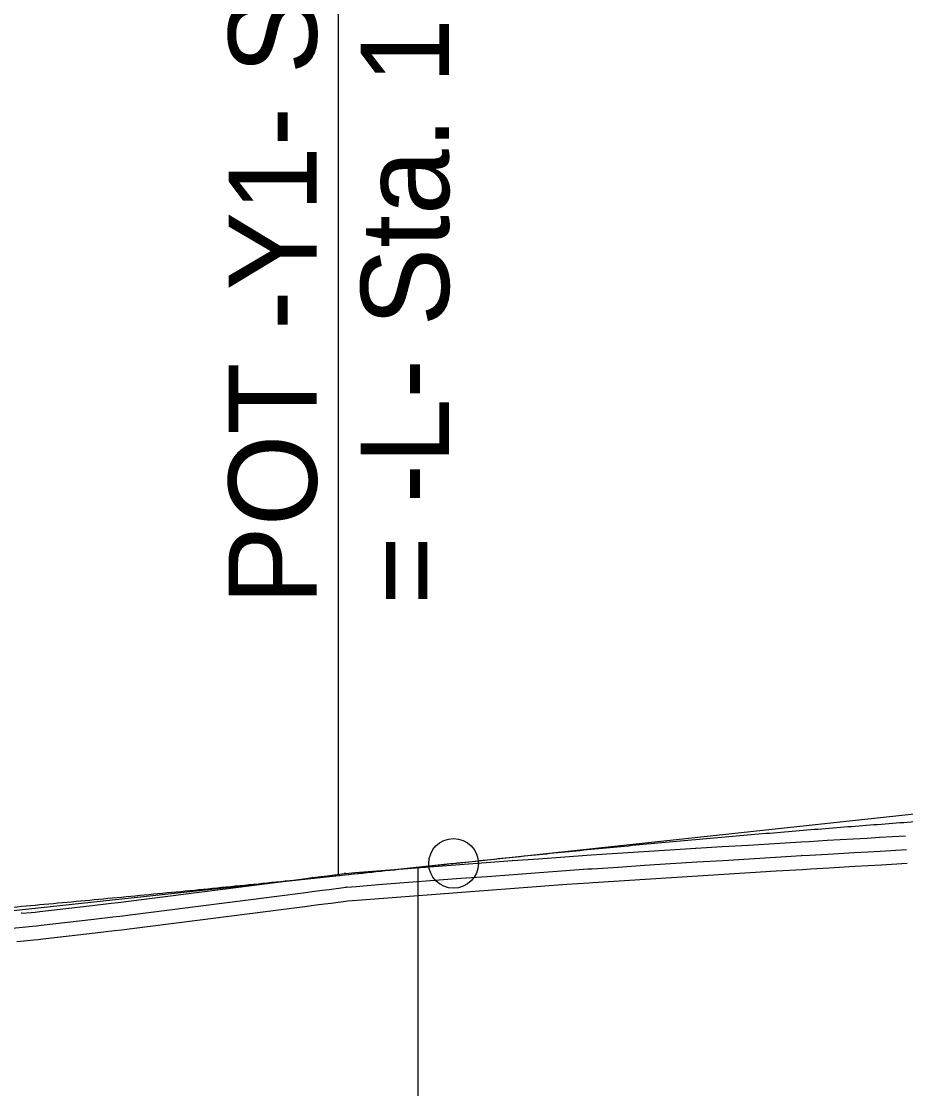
# Model space of a CAD drawing. Extents: x 1625686 to 1640492, y 1161393 to 1175642.
# Drawn here: x 1631055.1 to 1631135.3, y 1175003.6 to 1175100.4 of the extents above; entities that cross this region are included whole.
import ezdxf

# ---------------------------------------------------------------- set-up
doc = ezdxf.new("R2010")
doc.units = 0
for name, color, linetype in [('Exist Vertical Profile Ground Line', 7, 'Continuous'), ('Prop PFL Text', 7, 'Continuous'), ('Prop Vertical Profile Curve Label', 7, 'Continuous'), ('Prop Vertical Profile Grade', 7, 'Continuous'), ('Prop VPI Label', 7, 'Continuous'), ('Scratch_Level_1', 7, 'Continuous'), ('Scratch_Level_5', 7, 'Continuous')]:
    doc.layers.add(name, color=color, linetype=linetype)

msp = doc.modelspace()

# ---------------------------------------------------------------- linework, layer by layer
at = {"layer": 'Exist Vertical Profile Ground Line'}
msp.add_lwpolyline([(1631054.685, 1175016.921), (1631055.335, 1175016.981), (1631056.227, 1175017.063), (1631056.621, 1175017.098), (1631057.061, 1175017.149), (1631059.438, 1175017.425), (1631061.814, 1175017.702), (1631063.548, 1175017.904), (1631064.19, 1175017.985), (1631066.566, 1175018.285), (1631068.942, 1175018.585), (1631071.318, 1175018.887), (1631073.695, 1175019.189), (1631076.071, 1175019.492), (1631078.447, 1175019.797), (1631080.823, 1175020.102), (1631081.849, 1175020.234), (1631082.595, 1175020.325), (1631083.199, 1175020.405), (1631084.72, 1175020.605), (1631085.575, 1175020.672), (1631087.952, 1175020.857), (1631090.328, 1175021.04), (1631092.704, 1175021.222), (1631095.08, 1175021.401), (1631097.456, 1175021.579), (1631099.832, 1175021.755), (1631102.209, 1175021.93), (1631104.585, 1175022.102), (1631106.586, 1175022.246), (1631106.961, 1175022.271), (1631109.337, 1175022.426), (1631111.713, 1175022.579), (1631114.09, 1175022.73), (1631116.466, 1175022.88), (1631118.842, 1175023.028), (1631121.218, 1175023.174), (1631123.594, 1175023.318), (1631125.97, 1175023.46), (1631126.713, 1175023.504), (1631128.347, 1175023.6), (1631130.723, 1175023.736), (1631131.968, 1175023.807), (1631133.099, 1175023.874), (1631135.475, 1175024.013)], dxfattribs=at)
at = {"layer": 'Prop PFL Text'}
for p, q in [((1631083.884, 1175022.983), (1631083.884, 1175169.212)), ((1631091.115, 1174877.433), (1631091.115, 1175023.662))]:
    msp.add_line(p, q, dxfattribs=at)
at = {"layer": 'Prop Vertical Profile Curve Label'}
msp.add_circle((1631094.314, 1175024.002), 2.25, dxfattribs=at)
msp.add_circle((1631094.314, 1175024.002), 2.25, dxfattribs=at)
at = {"layer": 'Prop Vertical Profile Grade'}
for points in [[(1631094.314, 1175024.002), (1631099.714, 1175024.571), (1631105.114, 1175025.117), (1631110.514, 1175025.639), (1631115.914, 1175026.138), (1631121.314, 1175026.613), (1631126.714, 1175027.064), (1631132.114, 1175027.492), (1631137.514, 1175027.896), (1631142.914, 1175028.276), (1631148.314, 1175028.633), (1631153.714, 1175028.966), (1631159.114, 1175029.275), (1631164.514, 1175029.56), (1631169.914, 1175029.822), (1631175.314, 1175030.061), (1631180.714, 1175030.275), (1631186.114, 1175030.466), (1631191.514, 1175030.634), (1631196.914, 1175030.777), (1631202.314, 1175030.898), (1631207.714, 1175030.994), (1631213.114, 1175031.067), (1631218.514, 1175031.116), (1631223.914, 1175031.141), (1631229.314, 1175031.143), (1631234.714, 1175031.121), (1631240.114, 1175031.075), (1631245.514, 1175031.006), (1631250.914, 1175030.913), (1631256.314, 1175030.796), (1631261.714, 1175030.656), (1631267.114, 1175030.492), (1631272.514, 1175030.305), (1631277.914, 1175030.093), (1631283.314, 1175029.859), (1631288.714, 1175029.6), (1631294.114, 1175029.318), (1631299.514, 1175029.012), (1631304.914, 1175028.682), (1631310.314, 1175028.329), (1631315.714, 1175027.952), (1631321.114, 1175027.552), (1631326.514, 1175027.128), (1631331.914, 1175026.68), (1631337.314, 1175026.208), (1631342.714, 1175025.713), (1631348.114, 1175025.194), (1631353.514, 1175024.652), (1631358.914, 1175024.086), (1631364.314, 1175023.496)], [(1630764.314, 1175011.328), (1630770.914, 1175011.134), (1630777.514, 1175010.958), (1630784.114, 1175010.8), (1630790.714, 1175010.66), (1630797.314, 1175010.539), (1630803.914, 1175010.435), (1630810.514, 1175010.351), (1630817.114, 1175010.284), (1630823.714, 1175010.236), (1630830.314, 1175010.206), (1630836.914, 1175010.194), (1630843.514, 1175010.201), (1630850.114, 1175010.226), (1630856.714, 1175010.269), (1630863.314, 1175010.33), (1630869.914, 1175010.41), (1630876.514, 1175010.508), (1630883.114, 1175010.625), (1630889.714, 1175010.759), (1630896.314, 1175010.912), (1630902.914, 1175011.083), (1630909.514, 1175011.273), (1630916.114, 1175011.48), (1630922.714, 1175011.706), (1630929.314, 1175011.951), (1630935.914, 1175012.213), (1630942.514, 1175012.494), (1630949.114, 1175012.793), (1630955.714, 1175013.111), (1630962.314, 1175013.447), (1630968.914, 1175013.801), (1630975.514, 1175014.173), (1630982.114, 1175014.564), (1630988.714, 1175014.973), (1630995.314, 1175015.4), (1631001.914, 1175015.845), (1631008.514, 1175016.309), (1631015.114, 1175016.791), (1631021.714, 1175017.291), (1631028.314, 1175017.81), (1631034.914, 1175018.347), (1631041.514, 1175018.902), (1631048.114, 1175019.475), (1631054.714, 1175020.067), (1631061.314, 1175020.677), (1631067.914, 1175021.305), (1631074.514, 1175021.952), (1631081.114, 1175022.617), (1631087.714, 1175023.3), (1631094.314, 1175024.002)]]:
    msp.add_spline(points, degree=3, dxfattribs=at)
at = {"layer": 'Prop VPI Label'}
for q in [(1631226.58, 1175038.242), (1630932.048, 1175006.531)]:
    msp.add_line((1631094.314, 1175024.002), q, dxfattribs=at)
at = {"layer": 'Scratch_Level_1'}
for p, q in [((1631118.689, 1175025.523), (1631121.065, 1175025.669)), ((1631121.067, 1175025.669), (1631123.443, 1175025.813)), ((1631123.445, 1175025.814), (1631125.821, 1175025.956)), ((1631125.823, 1175025.956), (1631126.565, 1175026)), ((1631126.567, 1175026), (1631128.201, 1175026.095)), ((1631128.203, 1175026.095), (1631130.579, 1175026.232)), ((1631132.953, 1175026.37), (1631135.329, 1175026.508)), ((1631102.028, 1175024.423), (1631104.404, 1175024.596)), ((1631104.406, 1175024.596), (1631106.407, 1175024.739)), ((1631106.421, 1175024.74), (1631106.796, 1175024.765)), ((1631106.798, 1175024.765), (1631109.175, 1175024.92)), ((1631109.176, 1175024.92), (1631111.553, 1175025.074)), ((1631111.554, 1175025.074), (1631113.931, 1175025.225)), ((1631113.932, 1175025.225), (1631116.309, 1175025.375)), ((1631116.31, 1175025.375), (1631118.687, 1175025.523)), ((1631123.519, 1175024.566), (1631125.896, 1175024.708)), ((1631125.897, 1175024.708), (1631126.639, 1175024.752)), ((1631126.64, 1175024.752), (1631128.274, 1175024.847)), ((1631128.275, 1175024.848), (1631130.651, 1175024.984)), ((1631133.026, 1175025.122), (1631135.402, 1175025.261)), ((1631090.137, 1175023.533), (1631092.514, 1175023.715)), ((1631092.515, 1175023.715), (1631094.892, 1175023.894)), ((1631094.894, 1175023.894), (1631097.27, 1175024.072)), ((1631097.272, 1175024.072), (1631099.648, 1175024.249)), ((1631099.65, 1175024.249), (1631102.026, 1175024.423)), ((1631106.88, 1175023.518), (1631109.256, 1175023.673)), ((1631109.257, 1175023.673), (1631111.633, 1175023.826)), ((1631111.634, 1175023.826), (1631114.01, 1175023.978)), ((1631114.011, 1175023.978), (1631116.387, 1175024.127)), ((1631116.388, 1175024.127), (1631118.764, 1175024.275)), ((1631118.765, 1175024.275), (1631121.141, 1175024.421)), ((1631121.142, 1175024.421), (1631123.519, 1175024.566)), ((1631084.525, 1175023.097), (1631085.38, 1175023.165)), ((1631085.381, 1175023.165), (1631087.758, 1175023.35)), ((1631087.759, 1175023.35), (1631090.136, 1175023.533)), ((1631092.61, 1175022.468), (1631094.986, 1175022.648)), ((1631094.987, 1175022.648), (1631097.363, 1175022.826)), ((1631097.364, 1175022.826), (1631099.74, 1175023.002)), ((1631099.741, 1175023.002), (1631102.117, 1175023.176)), ((1631102.118, 1175023.176), (1631104.494, 1175023.349)), ((1631104.495, 1175023.349), (1631106.496, 1175023.493)), ((1631106.504, 1175023.493), (1631106.879, 1175023.518)), ((1631084.622, 1175021.851), (1631085.478, 1175021.918)), ((1631085.478, 1175021.918), (1631087.855, 1175022.103)), ((1631087.856, 1175022.103), (1631090.232, 1175022.287)), ((1631090.233, 1175022.287), (1631092.609, 1175022.468)), ((1631055.107, 1175019.471), (1631055.999, 1175019.552)), ((1631055.221, 1175018.226), (1631056.113, 1175018.307))]:
    msp.add_line(p, q, dxfattribs=at)
for points in [[(1631130.581, 1175026.232), (1631131.823, 1175026.303), (1631132.951, 1175026.369)], [(1631130.652, 1175024.984), (1631131.896, 1175025.055), (1631133.025, 1175025.122)], [(1631056.001, 1175019.552), (1631056.364, 1175019.585), (1631056.774, 1175019.633), (1631059.149, 1175019.908), (1631061.524, 1175020.185), (1631063.247, 1175020.386), (1631063.878, 1175020.465), (1631066.253, 1175020.765), (1631068.628, 1175021.065), (1631071.003, 1175021.367), (1631073.378, 1175021.669), (1631075.754, 1175021.972), (1631078.129, 1175022.276), (1631080.504, 1175022.582), (1631081.529, 1175022.714)], [(1631081.546, 1175022.716), (1631082.281, 1175022.805), (1631082.873, 1175022.883), (1631084.394, 1175023.084)], [(1631081.698, 1175021.475), (1631082.438, 1175021.565), (1631083.036, 1175021.644), (1631084.557, 1175021.844)], [(1631056.114, 1175018.307), (1631056.492, 1175018.342), (1631056.917, 1175018.391), (1631059.293, 1175018.667), (1631061.669, 1175018.943), (1631063.397, 1175019.145), (1631064.034, 1175019.225), (1631066.409, 1175019.525), (1631068.785, 1175019.825), (1631071.161, 1175020.127), (1631073.536, 1175020.429), (1631075.912, 1175020.732), (1631078.288, 1175021.037), (1631080.664, 1175021.342), (1631081.689, 1175021.474)], [(1631030.172, 1175015.955), (1631030.813, 1175016.011), (1631033.189, 1175016.222), (1631035.564, 1175016.434), (1631037.94, 1175016.647), (1631040.316, 1175016.861), (1631042.854, 1175017.09), (1631045.067, 1175017.292), (1631047.443, 1175017.509), (1631049.818, 1175017.727), (1631052.194, 1175017.946), (1631054.57, 1175018.165), (1631055.22, 1175018.226)]]:
    msp.add_lwpolyline(points, dxfattribs=at)
for centre, radius, start, end in [((1631121.218, 1175023.174), 2.5, 93.4746, 93.51747), ((1631123.594, 1175023.318), 2.5, 93.43169, 93.4746), ((1631125.97, 1175023.46), 2.5, 93.38873, 93.43169), ((1631126.713, 1175023.504), 2.5, 93.33274, 93.38873), ((1631128.347, 1175023.6), 2.5, 93.29095, 93.33274), ((1631130.723, 1175023.736), 2.5, 93.24912, 93.29095), ((1631133.099, 1175023.874), 2.5, 93.34509, 93.38704), ((1631104.585, 1175022.102), 2.5, 94.10418, 94.15337), ((1631106.586, 1175022.246), 2.5, 93.77378, 94.10418), ((1631106.961, 1175022.271), 2.5, 93.73117, 93.77378), ((1631109.337, 1175022.426), 2.5, 93.68852, 93.73117), ((1631111.713, 1175022.579), 2.5, 93.64582, 93.68852), ((1631114.09, 1175022.73), 2.5, 93.60308, 93.64582), ((1631116.466, 1175022.88), 2.5, 93.5603, 93.60308), ((1631118.842, 1175023.028), 2.5, 93.51747, 93.5603), ((1631125.97, 1175023.46), 1.25, 93.38873, 93.43169), ((1631126.713, 1175023.504), 1.25, 93.33274, 93.38873), ((1631128.347, 1175023.6), 1.25, 93.29095, 93.33274), ((1631130.723, 1175023.736), 1.25, 93.24912, 93.29095), ((1631133.099, 1175023.874), 1.25, 93.34509, 93.38704), ((1631092.704, 1175021.222), 2.5, 94.32362, 94.36605), ((1631095.08, 1175021.401), 2.5, 94.28113, 94.32362), ((1631097.456, 1175021.579), 2.5, 94.2386, 94.28113), ((1631099.832, 1175021.755), 2.5, 94.19601, 94.2386), ((1631102.209, 1175021.93), 2.5, 94.15337, 94.19601), ((1631109.337, 1175022.426), 1.25, 93.68852, 93.73117), ((1631111.713, 1175022.579), 1.25, 93.64582, 93.68852), ((1631114.09, 1175022.73), 1.25, 93.60308, 93.64582), ((1631116.466, 1175022.88), 1.25, 93.5603, 93.60308), ((1631118.842, 1175023.028), 1.25, 93.51747, 93.5603), ((1631121.218, 1175023.174), 1.25, 93.4746, 93.51747), ((1631123.594, 1175023.318), 1.25, 93.43169, 93.4746), ((1631081.849, 1175020.234), 2.5, 96.95013, 97.34369), ((1631084.72, 1175020.605), 2.5, 94.49303, 97.50913), ((1631085.575, 1175020.672), 2.5, 94.45076, 94.49303), ((1631087.952, 1175020.857), 2.5, 94.40843, 94.45076), ((1631090.328, 1175021.04), 2.5, 94.36605, 94.40843), ((1631095.08, 1175021.401), 1.25, 94.28113, 94.32362), ((1631097.456, 1175021.579), 1.25, 94.2386, 94.28113), ((1631099.832, 1175021.755), 1.25, 94.19601, 94.2386), ((1631102.209, 1175021.93), 1.25, 94.15337, 94.19601), ((1631104.585, 1175022.102), 1.25, 94.10418, 94.15337), ((1631106.586, 1175022.246), 1.25, 93.77378, 94.10418), ((1631106.961, 1175022.271), 1.25, 93.73117, 93.77378), ((1631084.72, 1175020.605), 1.25, 94.49303, 97.50913), ((1631085.575, 1175020.672), 1.25, 94.45076, 94.49303), ((1631087.952, 1175020.857), 1.25, 94.40843, 94.45076), ((1631090.328, 1175021.04), 1.25, 94.36605, 94.40843), ((1631092.704, 1175021.222), 1.25, 94.32362, 94.36605), ((1631081.849, 1175020.234), 1.25, 96.95013, 97.34369), ((1631055.335, 1175016.981), 2.5, 95.23039, 95.3055), ((1631056.227, 1175017.063), 2.5, 95.19818, 95.23039), ((1631055.335, 1175016.981), 1.25, 95.23039, 95.3055), ((1631056.227, 1175017.063), 1.25, 95.19818, 95.23039)]:
    msp.add_arc(centre, radius, start, end, dxfattribs=at)
at = {"layer": 'Scratch_Level_5'}
msp.add_lwpolyline([(1631054.685, 1175016.921), (1631055.335, 1175016.981), (1631056.227, 1175017.063), (1631056.621, 1175017.098), (1631057.061, 1175017.149), (1631059.438, 1175017.425), (1631061.814, 1175017.702), (1631063.548, 1175017.904), (1631064.19, 1175017.985), (1631066.566, 1175018.285), (1631068.942, 1175018.585), (1631071.318, 1175018.887), (1631073.695, 1175019.189), (1631076.071, 1175019.492), (1631078.447, 1175019.797), (1631080.823, 1175020.102), (1631081.849, 1175020.234), (1631082.595, 1175020.325), (1631083.199, 1175020.405), (1631084.72, 1175020.605), (1631085.575, 1175020.672), (1631087.952, 1175020.857), (1631090.328, 1175021.04), (1631092.704, 1175021.222), (1631095.08, 1175021.401), (1631097.456, 1175021.579), (1631099.832, 1175021.755), (1631102.209, 1175021.93), (1631104.585, 1175022.102), (1631106.586, 1175022.246), (1631106.961, 1175022.271), (1631109.337, 1175022.426), (1631111.713, 1175022.579), (1631114.09, 1175022.73), (1631116.466, 1175022.88), (1631118.842, 1175023.028), (1631121.218, 1175023.174), (1631123.594, 1175023.318), (1631125.97, 1175023.46), (1631126.713, 1175023.504), (1631128.347, 1175023.6), (1631130.723, 1175023.736), (1631131.968, 1175023.807), (1631133.099, 1175023.874), (1631135.475, 1175024.013)], dxfattribs=at)

# ---------------------------------------------------------------- texts
at = {"layer": 'Prop PFL Text'}
for s, p in [('POT -Y1- Sta. 17+37.23', (1631081.903, 1175047.453)), ('= -L- Sta. 18+66.47', (1631093.903, 1175047.453))]:
    msp.add_text(s, height=8, rotation=90, dxfattribs=at).set_placement(p)

doc.saveas('drawing.dxf')
